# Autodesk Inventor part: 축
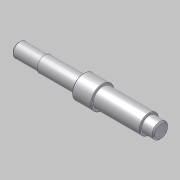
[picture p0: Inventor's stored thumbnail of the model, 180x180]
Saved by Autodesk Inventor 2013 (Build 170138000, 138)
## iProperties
Created: 2013-08
Part Number: 축
Document SubType Name: Modeling
Designer: 한국산업디자인학원
Density: 1 g/cm^3
Material: 일반
Author: 한국산업디자인학원
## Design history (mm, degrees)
sketch "스케치1"
  geometry: L1 (31.5, 63.7)-(31.5, 36.3) reference; L2 (23.5, 41.392)-(23.5, 58.608) reference; L3 (31.2, 56)-(23.8, 56) reference; L4 (-27.8, 56)-(-35.2, 56) reference; L5 (32.5, 50)-(-77.5, 50); L6 (32.5, 50)-(32.5, 56); L7 (32.5, 56)-(23.5, 56); L8 (23.5, 56)-(23.5, 57.5); L9 (23.5, 57.5)-(-7.5, 57.5); L10 (-7.5, 57.5)-(-7.5, 59); L11 (-7.5, 59)-(-22.5, 59); L12 (-22.5, 59)-(-22.5, 56); L13 (-22.5, 56)-(-52.5, 56); L14 (-52.5, 56)-(-52.5, 55.5); L15 (-52.5, 55.5)-(-77.5, 55.5); L16 (-77.5, 55.5)-(-77.5, 50); L17 (-1.5, 57.5)-(-1.5, 54.5); L18 (-1.5, 54.5)-(12.5, 54.5); L19 (12.5, 54.5)-(12.5, 57.5); L20 (-22.5, 50)-(-22.5, 90) reference; 2 further points
  constraints: 34 end point, 9 perpendicular, 5 point on line, 4 parallel, 3 collinear, 2 horizontal, 1 midpoint, 4 other
  dimensions: "d0" = 1 distance from line of L5.start L1; "d1" = 18 diameter of L11 L5; "d2" = 15 diameter of L9 L5; "d5" = 25 distance of L14.end L15.end; "d6" = 11 diameter of L15 L5; "d7" = 3 distance between parallel lines of L18 L9; "d8" = 14 distance between parallel lines of L19 L17; "d9" = 6 distance between parallel lines of L17 L10; "d38" = 15 distance of L10.end L11.end
revolve "회전1" sketch "스케치1" stored, may be unused: angle "d10" = 90 deg
sketch "스케치2"
  geometry: L1 (-7.5, 57.5)-(23.5, 57.5) reference; L2 (-7.5, 41)-(-7.5, 59) reference; L3 (-4.5, 57.5)-(-4.5, 54.5); L4 (-4.5, 54.5)-(11.5, 54.5); L5 (11.5, 54.5)-(11.5, 57.5); L6 (-77.5, 55.5)-(-52.5, 55.5) reference; L7 (-73.5, 55.5)-(-73.5, 53); L8 (-73.5, 53)-(-61.5, 53); L9 (-61.5, 53)-(-61.5, 55.5); L10 (-77.5, 44.5)-(-77.5, 55.5) reference; 1 further point
  constraints: 12 end point, 4 perpendicular, 4 point on line, 2 parallel
  dimensions: "d11" = 3 distance between parallel lines of L4 L1; "d12" = 3 distance between parallel lines of L3 L2; "d13" = 16 distance of L3.end L4.end; "d23" = 2.5 distance between parallel lines of L8 L6; "d24" = 12 distance of L7.end L8.end; "d25" = 4 distance between parallel lines of L7 L10
extrude "돌출1" cut sketch "스케치2" stored distance "d14" = 5; taper "d15" = 0 deg
fillet "모깎기1" dims "d16" = 2.5
chamfer "모따기1" distance "d17" = 1; stored, may be unused: second distance "d18" = 2, angle "d19" = 45 deg
chamfer "모따기2" distance "d20" = 0.5; stored, may be unused: second distance "d21" = 2, angle "d22" = 45 deg
extrude "돌출2" cut sketch "스케치2" stored distance "d26" = 4; taper "d27" = 0 deg
fillet "모깎기2" dims "d28" = 2
hole "구멍1" diameter "d31" = 4.134; stored, may be unused: countersink angle "d35" = 90 deg, drill point angle "d37" = 118 deg; dims "d29" = 10, "d30" = 10, "d32" = 13, "d33" = 4, "d34" = 2, "d36" = 15
node "솔리드1"
node "참조1"
node "참조2"
node "참조4"
